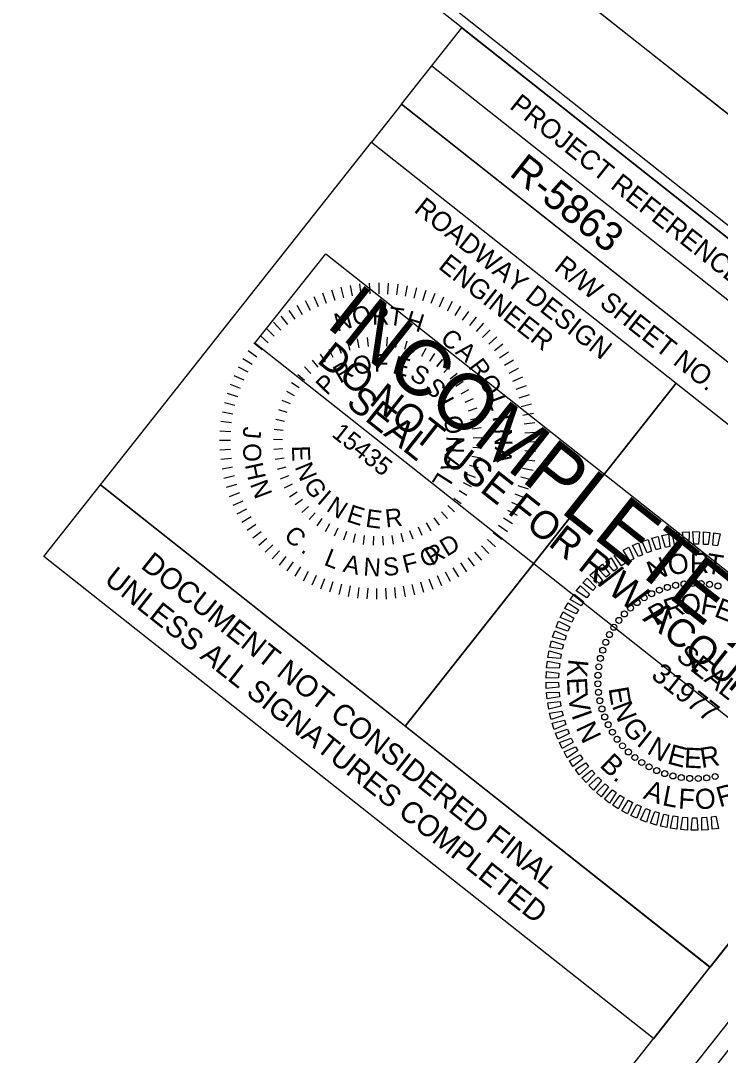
# Model space of a CAD drawing. Extents: x 556999 to 559002, y 505273 to 507273.
# Drawn here: x 558703.1 to 558883.2, y 506079.3 to 506345.6 of the extents above; entities that cross this region are included whole.
import ezdxf

# ---------------------------------------------------------------- set-up
doc = ezdxf.new("R2010")
doc.units = 0
for name, color, linetype in [('Old_Level_21', 7, 'Continuous'), ('Sheet Border Standard 30in CELL', 7, 'Continuous'), ('Sheet Cutting Line CELL', 7, 'Continuous'), ('Sheet Data Field CELL', 7, 'Continuous'), ('Sheet Plot Border Inside CELL', 7, 'Continuous'), ('Sheet Plot Border Outside CELL', 7, 'Continuous'), ('Sheet Sticker Exception Certification CELL', 7, 'Continuous'), ('Sheet Sticker Incomplete CELL', 7, 'Continuous')]:
    doc.layers.add(name, color=color, linetype=linetype)

msp = doc.modelspace()

# ---------------------------------------------------------------- linework, layer by layer
at = {"layer": 'Old_Level_21'}
for p, q in [((558783.1, 506276.32), (558783.91, 506273.67)), ((558785.47, 506276.97), (558786.12, 506274.27)), ((558787.88, 506277.47), (558788.36, 506274.74)), ((558790.31, 506277.83), (558790.63, 506275.07)), ((558792.76, 506278.04), (558792.91, 506275.27)), ((558795.22, 506278.1), (558795.21, 506275.32)), ((558797.68, 506278.01), (558797.5, 506275.24)), ((558800.13, 506277.77), (558799.78, 506275.02)), ((558802.56, 506277.39), (558802.04, 506274.66)), ((558804.96, 506276.85), (558804.28, 506274.17)), ((558807.33, 506276.18), (558806.49, 506273.53)), ((558776.27, 506273.54), (558777.55, 506271.08)), ((558778.49, 506274.61), (558779.61, 506272.07)), ((558780.77, 506275.54), (558781.73, 506272.93)), ((558809.65, 506275.37), (558808.64, 506272.78)), ((558811.92, 506274.41), (558810.76, 506271.89)), ((558814.12, 506273.32), (558812.81, 506270.87)), ((558772.05, 506271.03), (558773.62, 506268.73)), ((558774.12, 506272.35), (558775.54, 506269.96)), ((558816.25, 506272.1), (558814.8, 506269.74)), ((558818.31, 506270.75), (558816.72, 506268.48)), ((558768.16, 506268.02), (558769.99, 506265.93)), ((558770.06, 506269.58), (558771.76, 506267.39)), ((558820.28, 506269.28), (558818.56, 506267.11)), ((558822.16, 506267.7), (558820.31, 506265.63)), ((558766.36, 506266.34), (558768.31, 506264.37)), ((558823.94, 506266), (558821.97, 506264.05)), ((558763.08, 506262.68), (558765.25, 506260.95)), ((558764.67, 506264.56), (558766.73, 506262.71)), ((558787.15, 506263.05), (558787.82, 506260.83)), ((558789.66, 506263.68), (558790.12, 506261.42)), ((558792.23, 506264.07), (558792.47, 506261.77)), ((558794.82, 506264.22), (558794.83, 506261.9)), ((558797.41, 506264.11), (558797.2, 506261.8)), ((558799.98, 506263.75), (558799.54, 506261.48)), ((558802.5, 506263.14), (558801.85, 506260.92)), ((558804.95, 506262.3), (558804.09, 506260.15)), ((558825.62, 506264.2), (558823.53, 506262.37)), ((558827.18, 506262.3), (558824.99, 506260.6)), ((558761.61, 506260.7), (558763.88, 506259.11)), ((558780.14, 506259.73), (558781.42, 506257.81)), ((558782.36, 506261.06), (558783.45, 506259.02)), ((558784.71, 506262.17), (558785.59, 506260.03)), ((558807.31, 506261.22), (558806.24, 506259.16)), ((558809.55, 506259.92), (558808.29, 506257.98)), ((558828.63, 506260.31), (558826.34, 506258.75)), ((558760.26, 506258.65), (558762.63, 506257.2)), ((558778.05, 506258.2), (558779.51, 506256.4)), ((558811.66, 506258.41), (558810.22, 506256.6)), ((558810.22, 506256.6), (558811.66, 506258.41)), ((558829.95, 506258.24), (558827.57, 506256.82)), ((558757.95, 506254.31), (558760.47, 506253.15)), ((558759.04, 506256.51), (558761.49, 506255.21)), ((558774.36, 506254.56), (558776.14, 506253.08)), ((558776.12, 506256.47), (558777.74, 506254.82)), ((558813.61, 506256.7), (558812.01, 506255.03)), ((558815.39, 506254.81), (558813.63, 506253.31)), ((558831.15, 506256.09), (558828.68, 506254.81)), ((558756.99, 506252.04), (558759.59, 506251.04)), ((558772.8, 506252.49), (558774.71, 506251.18)), ((558816.97, 506252.76), (558815.08, 506251.43)), ((558832.21, 506253.87), (558829.67, 506252.75)), ((558756.18, 506249.72), (558758.83, 506248.88)), ((558771.45, 506250.27), (558773.48, 506249.16)), ((558818.36, 506250.57), (558816.34, 506249.43)), ((558833.14, 506251.59), (558830.54, 506250.63)), ((558833.93, 506249.26), (558831.28, 506248.45)), ((558755.51, 506247.35), (558758.2, 506246.67)), ((558770.31, 506247.94), (558772.44, 506247.03)), ((558819.52, 506248.25), (558817.41, 506247.31)), ((558834.57, 506246.89), (558831.88, 506246.24)), ((558754.97, 506244.95), (558757.7, 506244.44)), ((558769.41, 506245.51), (558771.61, 506244.81)), ((558820.46, 506245.83), (558818.26, 506245.1)), ((558835.08, 506244.48), (558832.35, 506244)), ((558754.59, 506242.52), (558757.34, 506242.17)), ((558768.75, 506243.01), (558771.01, 506242.52)), ((558821.15, 506243.33), (558818.89, 506242.82)), ((558835.43, 506242.05), (558832.68, 506241.73)), ((558754.35, 506240.07), (558757.12, 506239.89)), ((558768.32, 506240.45), (558770.62, 506240.18)), ((558821.6, 506240.78), (558819.31, 506240.49)), ((558835.64, 506239.6), (558832.87, 506239.45)), ((558754.27, 506237.62), (558757.04, 506237.6)), ((558768.15, 506237.86), (558770.46, 506237.82)), ((558821.76, 506235.6), (558819.45, 506235.75)), ((558821.81, 506238.19), (558819.5, 506238.12)), ((558835.7, 506237.14), (558832.93, 506237.16)), ((558754.33, 506235.16), (558757.1, 506235.31)), ((558754.54, 506232.71), (558757.29, 506233.03)), ((558768.23, 506235.27), (558770.53, 506235.45)), ((558768.56, 506232.7), (558770.84, 506233.1)), ((558821.47, 506233.03), (558819.18, 506233.4)), ((558835.61, 506234.68), (558832.85, 506234.86)), ((558754.89, 506230.28), (558757.62, 506230.76)), ((558769.13, 506230.17), (558771.36, 506230.79)), ((558820.92, 506230.49), (558818.69, 506231.08)), ((558835.38, 506232.23), (558832.62, 506232.58)), ((558755.39, 506227.86), (558758.09, 506228.51)), ((558769.95, 506227.71), (558772.11, 506228.54)), ((558820.13, 506228.02), (558817.97, 506228.83)), ((558834.46, 506227.4), (558831.77, 506228.08)), ((558834.99, 506229.8), (558832.26, 506230.32)), ((558756.04, 506225.49), (558758.69, 506226.3)), ((558771, 506225.34), (558773.07, 506226.37)), ((558819.12, 506225.63), (558817.03, 506226.65)), ((558833.79, 506225.03), (558831.14, 506225.88)), ((558756.82, 506223.16), (558759.43, 506224.13)), ((558772.28, 506223.07), (558774.24, 506224.31)), ((558775.58, 506222.38), (558773.75, 506220.96)), ((558816.41, 506221.22), (558814.56, 506222.61)), ((558817.87, 506223.36), (558815.9, 506224.57)), ((558832.97, 506222.72), (558830.38, 506223.72)), ((558757.75, 506220.88), (558760.29, 506222.01)), ((558758.82, 506218.67), (558761.28, 506219.94)), ((558775.45, 506218.98), (558777.13, 506220.57)), ((558814.75, 506219.22), (558813.05, 506220.79)), ((558832.02, 506220.45), (558829.49, 506221.6)), ((558760.01, 506216.52), (558762.4, 506217.94)), ((558777.31, 506217.18), (558778.83, 506218.92)), ((558779.34, 506215.57), (558780.69, 506217.45)), ((558810.89, 506215.76), (558809.52, 506217.62)), ((558811.42, 506219.18), (558812.97, 506217.46)), ((558829.7, 506216.11), (558827.34, 506217.56)), ((558830.93, 506218.24), (558828.48, 506219.55)), ((558761.33, 506214.44), (558763.63, 506216.01)), ((558781.52, 506214.16), (558782.68, 506216.16)), ((558783.83, 506212.97), (558784.79, 506215.08)), ((558806.44, 506213.11), (558805.46, 506215.2)), ((558808.73, 506214.33), (558807.55, 506216.31)), ((558828.36, 506214.05), (558826.08, 506215.64)), ((558762.78, 506212.45), (558764.98, 506214.15)), ((558764.35, 506210.56), (558766.43, 506212.38)), ((558786.23, 506212.01), (558786.99, 506214.2)), ((558788.72, 506211.28), (558789.26, 506213.53)), ((558791.27, 506210.8), (558791.59, 506213.09)), ((558793.85, 506210.57), (558793.95, 506212.88)), ((558796.45, 506210.58), (558796.32, 506212.89)), ((558799.03, 506210.85), (558798.68, 506213.13)), ((558801.57, 506211.36), (558801, 506213.6)), ((558804.05, 506212.12), (558803.27, 506214.29)), ((558825.3, 506210.2), (558823.23, 506212.05)), ((558826.89, 506212.08), (558824.71, 506213.8)), ((558766.02, 506208.76), (558767.99, 506210.71)), ((558767.8, 506207.06), (558769.65, 506209.13)), ((558823.6, 506208.42), (558821.65, 506210.39)), ((558769.68, 506205.47), (558771.41, 506207.65)), ((558819.91, 506205.18), (558818.21, 506207.37)), ((558821.81, 506206.74), (558819.98, 506208.83)), ((558771.66, 506204), (558773.25, 506206.28)), ((558773.72, 506202.66), (558775.16, 506205.02)), ((558775.85, 506201.43), (558777.15, 506203.88)), ((558815.85, 506202.41), (558814.42, 506204.79)), ((558817.92, 506203.73), (558816.35, 506206.03)), ((558778.05, 506200.35), (558779.21, 506202.87)), ((558780.32, 506199.39), (558781.32, 506201.98)), ((558782.64, 506198.57), (558783.48, 506201.22)), ((558806.87, 506198.43), (558806.06, 506201.09)), ((558809.2, 506199.22), (558808.23, 506201.82)), ((558811.48, 506200.15), (558810.35, 506202.69)), ((558813.69, 506201.22), (558812.42, 506203.68)), ((558785.01, 506197.9), (558785.69, 506200.59)), ((558787.41, 506197.37), (558787.93, 506200.1)), ((558789.84, 506196.98), (558790.19, 506199.74)), ((558792.29, 506196.75), (558792.47, 506199.52)), ((558794.74, 506196.66), (558794.76, 506199.43)), ((558797.21, 506196.72), (558797.05, 506199.49)), ((558799.65, 506196.93), (558799.34, 506199.69)), ((558802.09, 506197.28), (558801.6, 506200.02)), ((558804.5, 506197.79), (558803.85, 506200.48))]:
    msp.add_line(p, q, dxfattribs=at)
for points in [[(558864.34, 506208.61), (558863.02, 506211.57), (558864.61, 506212.1), (558865.45, 506209.02)], [(558866.67, 506209.4), (558865.56, 506212.44), (558867.18, 506212.86), (558867.8, 506209.73)], [(558869.05, 506210.02), (558868.15, 506213.13), (558869.8, 506213.44), (558870.2, 506210.27)], [(558871.46, 506210.47), (558870.79, 506213.64), (558872.45, 506213.83), (558872.63, 506210.64)], [(558873.9, 506210.76), (558873.45, 506213.96), (558875.12, 506214.04), (558875.08, 506210.84)], [(558876.36, 506210.87), (558876.13, 506214.1), (558877.81, 506214.06), (558877.54, 506210.87)], [(558878.82, 506210.81), (558878.81, 506214.05), (558880.48, 506213.89), (558880, 506210.73)], [(558881.26, 506210.58), (558881.49, 506213.81), (558883.14, 506213.54), (558882.44, 506210.42)], [(558859.87, 506206.57), (558858.16, 506209.31), (558859.65, 506210.06), (558860.92, 506207.12)], [(558862.07, 506207.67), (558860.55, 506210.52), (558862.1, 506211.17), (558863.15, 506208.15)], [(558855.73, 506203.92), (558853.65, 506206.39), (558855.03, 506207.34), (558856.69, 506204.61)], [(558857.76, 506205.31), (558855.85, 506207.93), (558857.3, 506208.78), (558858.76, 506205.94)], [(558852.01, 506200.72), (558849.6, 506202.88), (558850.83, 506204.01), (558852.86, 506201.54)], [(558853.81, 506202.38), (558851.57, 506204.71), (558852.87, 506205.75), (558854.72, 506203.14)], [(558850.32, 506198.93), (558847.77, 506200.92), (558848.92, 506202.14), (558851.11, 506199.81)], [(558848.76, 506197.03), (558846.08, 506198.84), (558847.14, 506200.13), (558849.49, 506197.96)], [(558846.06, 506192.93), (558843.15, 506194.34), (558844.02, 506195.77), (558846.65, 506193.95)], [(558847.34, 506195.02), (558844.53, 506196.64), (558845.5, 506198.01), (558848, 506196.01)], [(558844.93, 506190.74), (558841.93, 506191.95), (558842.7, 506193.44), (558845.44, 506191.81)], [(558843.95, 506188.49), (558840.88, 506189.48), (558841.54, 506191.02), (558844.39, 506189.58)], [(558843.14, 506186.17), (558840, 506186.95), (558840.55, 506188.53), (558843.5, 506187.29)], [(558842.48, 506183.8), (558839.3, 506184.36), (558839.74, 506185.97), (558842.77, 506184.95)], [(558842, 506181.39), (558838.78, 506181.72), (558839.11, 506183.37), (558842.2, 506182.55)], [(558841.68, 506178.95), (558838.45, 506179.06), (558838.67, 506180.72), (558841.81, 506180.13)], [(558841.54, 506176.49), (558838.31, 506176.38), (558838.41, 506178.05), (558841.58, 506177.68)], [(558841.57, 506174.04), (558838.35, 506173.7), (558838.33, 506175.37), (558841.53, 506175.22)], [(558841.77, 506171.59), (558838.58, 506171.02), (558838.45, 506172.69), (558841.64, 506172.76)], [(558842.14, 506169.16), (558839, 506168.37), (558838.75, 506170.03), (558841.93, 506170.32)], [(558842.67, 506166.76), (558839.6, 506165.76), (558839.23, 506167.39), (558842.39, 506167.91)], [(558843.38, 506164.4), (558840.38, 506163.19), (558839.9, 506164.79), (558843.01, 506165.53)], [(558844.24, 506162.1), (558841.34, 506160.68), (558840.75, 506162.25), (558843.8, 506163.2)], [(558845.27, 506159.87), (558842.47, 506158.25), (558841.77, 506159.77), (558844.75, 506160.93)], [(558846.45, 506157.71), (558843.77, 506155.9), (558842.96, 506157.37), (558845.85, 506158.73)], [(558847.77, 506155.64), (558845.22, 506153.65), (558844.32, 506155.06), (558847.11, 506156.62)], [(558849.24, 506153.67), (558846.84, 506151.5), (558845.84, 506152.85), (558848.51, 506154.6)], [(558850.84, 506151.8), (558848.59, 506149.47), (558847.5, 506150.75), (558850.05, 506152.68)], [(558852.57, 506150.05), (558850.49, 506147.57), (558849.31, 506148.77), (558851.71, 506150.87)], [(558854.41, 506148.43), (558852.51, 506145.81), (558851.25, 506146.92), (558853.5, 506149.19)], [(558856.36, 506146.94), (558854.65, 506144.19), (558853.32, 506145.21), (558855.41, 506147.63)], [(558858.42, 506145.58), (558856.9, 506142.73), (558855.5, 506143.65), (558857.41, 506146.21)], [(558860.56, 506144.38), (558859.25, 506141.42), (558857.79, 506142.24), (558859.51, 506144.93)], [(558862.78, 506143.33), (558861.68, 506140.29), (558860.16, 506141), (558861.7, 506143.81)], [(558865.07, 506142.43), (558864.18, 506139.32), (558862.62, 506139.93), (558863.96, 506142.83)], [(558867.42, 506141.7), (558866.75, 506138.53), (558865.15, 506139.03), (558866.28, 506142.02)], [(558869.81, 506141.13), (558869.36, 506137.93), (558867.73, 506138.31), (558868.65, 506141.37)], [(558872.23, 506140.73), (558872.01, 506137.5), (558870.36, 506137.77), (558871.06, 506140.89)], [(558874.68, 506140.5), (558874.68, 506137.26), (558873.02, 506137.42), (558873.5, 506140.58)], [(558877.14, 506140.44), (558877.37, 506137.21), (558875.69, 506137.25), (558875.96, 506140.44)], [(558879.59, 506140.55), (558880.05, 506137.35), (558878.37, 506137.27), (558878.41, 506140.47)], [(558882.04, 506140.84), (558882.71, 506137.67), (558881.05, 506137.48), (558880.86, 506140.67)]]:
    msp.add_lwpolyline(points, close=True, dxfattribs=at)
for centre in [(558871.66, 506200.26), (558873.83, 506200.61), (558876.02, 506200.77), (558878.21, 506200.74), (558880.39, 506200.52), (558865.47, 506198.11), (558867.47, 506199.01), (558869.54, 506199.72), (558882.54, 506200.1), (558861.74, 506195.81), (558863.56, 506197.04), (558858.47, 506192.9), (558860.04, 506194.42), (558857.04, 506191.24), (558854.63, 506187.58), (558855.75, 506189.46), (558853.68, 506185.6), (558852.9, 506183.56), (558851.89, 506179.29), (558852.3, 506181.45), (558851.67, 506177.11), (558851.63, 506174.92), (558851.79, 506172.74), (558852.14, 506170.57), (558852.68, 506168.45), (558853.4, 506166.38), (558854.3, 506164.38), (558855.37, 506162.46), (558856.6, 506160.65), (558857.98, 506158.95), (558859.51, 506157.38), (558861.17, 506155.94), (558862.94, 506154.66), (558864.83, 506153.54), (558866.8, 506152.58), (558868.85, 506151.8), (558870.96, 506151.21), (558873.11, 506150.79), (558875.29, 506150.57), (558877.48, 506150.54), (558879.67, 506150.7), (558881.83, 506151.05)]:
    msp.add_circle(centre, 0.777, dxfattribs=at)
at = {"layer": 'Sheet Border Standard 30in CELL'}
for p, q in [((558808.87, 506333.95), (558965.79, 506209.87)), ((558801.12, 506324.14), (558793.36, 506314.33)), ((558801.12, 506324.14), (558958.04, 506200.06)), ((558801.12, 506324.14), (558958.04, 506200.06)), ((558871.84, 506252.28), (558802.1, 506164.07))]:
    msp.add_line(p, q, dxfattribs=at)
for points in [[(558973.57, 506219.71), (557796.95, 507150.06), (557145.7, 506326.43), (558322.33, 505396.07)], [(558816.65, 506343.79), (558973.57, 506219.71), (558958.04, 506200.06), (558801.12, 506324.14)], [(558793.36, 506314.33), (558871.84, 506252.28), (558802.07, 506164.03), (558723.59, 506226.09)], [(558871.84, 506252.28), (558950.28, 506190.26), (558880.51, 506102.01), (558802.07, 506164.03)]]:
    msp.add_lwpolyline(points, close=True, dxfattribs=at)
at = {"layer": 'Sheet Cutting Line CELL'}
msp.add_line((559002.42, 506228.78), (557681.46, 507273.25), dxfattribs=at)
at = {"layer": 'Sheet Plot Border Inside CELL'}
msp.add_lwpolyline([(558984.96, 506213.96), (557677.73, 507247.58), (557023.32, 506419.94), (558330.55, 505386.32)], close=True, dxfattribs=at)
at = {"layer": 'Sheet Plot Border Outside CELL'}
msp.add_lwpolyline([(559002.42, 506228.78), (557681.46, 507273.25), (556999.2, 506410.4), (558320.16, 505365.92)], close=True, dxfattribs=at)
at = {"layer": 'Sheet Sticker Exception Certification CELL'}
for p, q in [((558709.01, 506207.65), (558723.59, 506226.09)), ((558723.59, 506226.09), (558880.5, 506102.02)), ((558865.92, 506083.58), (558709.01, 506207.65)), ((558880.49, 506102.01), (558865.92, 506083.57))]:
    msp.add_line(p, q, dxfattribs=at)
at = {"layer": 'Sheet Sticker Incomplete CELL'}
msp.add_lwpolyline([(558763.37, 506262.57), (558781.59, 506285.61), (558925.73, 506171.64), (558907.51, 506148.6)], close=True, dxfattribs=at)

# ---------------------------------------------------------------- texts
at = {"layer": 'Old_Level_21'}
for s, height, rotation, p in [('N', 4.62, 15.2636, (558784.48, 506265.54)), ('O', 4.62, 13.3041, (558788.98, 506266.95)), ('R', 4.62, 0.2474, (558793.54, 506267.31)), ('T', 4.62, 352.0864, (558797.58, 506267.4)), ('H', 4.62, 342.6545, (558801.75, 506266.67)), ('C', 4.62, 318.9438, (558810.8, 506263.28)), ('A', 4.62, 318.9438, (558814.7, 506260.07)), ('F', 4.62, 359.8274, (558794, 506255.22)), ('R', 4.62, 30.4199, (558785.27, 506252.09)), ('O', 4.62, 15.1237, (558789.28, 506254.21)), ('E', 4.62, 344.5312, (558798.53, 506254.97)), ('R', 4.62, 306.9345, (558818.12, 506256.49)), ('P', 4.62, 45.7162, (558781.87, 506248.94)), ('S', 4.62, 329.235, (558802.92, 506253.52)), ('O', 4.62, 303.8777, (558820.8, 506252.67)), ('S', 4.62, 313.9387, (558806.77, 506250.95)), ('SEAL', 6.938, 321.5868, (558786.54, 506246.73)), ('L', 4.62, 290.7414, (558823.2, 506248.13)), ('I', 4.62, 298.6425, (558810, 506247.12)), ('O', 4.62, 283.3462, (558811.8, 506243.39)), ('I', 4.62, 281.1659, (558824.46, 506243.71)), ('J', 4.62, 265.5218, (558760.43, 506241.22)), ('15435', 4.622, 321.5868, (558782.88, 506238.78)), ('N', 4.62, 271.8715, (558824.92, 506240.57)), ('O', 4.62, 273.5937, (558760.21, 506236.69)), ('E', 4.62, 271.6569, (558772.88, 506236.17)), ('N', 4.62, 268.05, (558812.67, 506238.75)), ('A', 4.62, 262.1039, (558825.19, 506236)), ('A', 4.62, 252.7537, (558812.3, 506234.21)), ('H', 4.62, 282.2364, (558760.75, 506231.3)), ('N', 4.62, 292.512, (558773.53, 506230.74)), ('G', 4.62, 301.2782, (558775.73, 506226.23)), ('L', 4.62, 237.4575, (558810.63, 506229.7)), ('N', 4.62, 290.909, (558762.02, 506226.31)), ('I', 4.62, 319.373, (558779.12, 506221.65)), ('N', 4.62, 327.0027, (558781.48, 506219.58)), ('E', 4.62, 342.3948, (558786.71, 506216.75)), ('E', 4.62, 352.3806, (558791.65, 506215.35)), ('R', 4.62, 6.1517, (558797.11, 506215.14)), ('C', 4.62, 317.6768, (558770.54, 506212.65)), (' RD', 4.622, 31.2593, (558807.49, 506204.33)), ('.', 4.62, 325.4191, (558774.96, 506208.98)), ('L', 4.62, 338.2034, (558780.87, 506205.61)), ('O ', 4.622, 22.5865, (558806.95, 506204.73)), ('A', 4.62, 347.206, (558785.83, 506203.83)), ('N', 4.62, 356.0286, (558791.16, 506202.82)), ('S', 4.62, 4.9113, (558796.54, 506202.65)), ('F', 4.62, 13.7939, (558802, 506203.33)), ('N', 5.18, 20.2083, (558865.43, 506201.16)), ('O', 5.18, 9.9979, (558870.13, 506202.76)), ('R', 5.18, 359.2727, (558875.29, 506203.52)), ('T', 5.18, 351.0641, (558879.28, 506203.44)), ('P', 5.18, 30.0082, (558866.56, 506189.67)), ('R', 5.18, 18.2459, (558869.63, 506191.45)), ('O', 5.18, 6.1465, (558873.1, 506192.59)), ('F', 5.18, 350.3377, (558877.85, 506192.94)), ('E', 5.18, 338.6598, (558881.33, 506192.36)), ('SEAL', 5.181, 321.6738, (558871.48, 506181.47)), ('K', 5.18, 264.2876, (558844.14, 506181.44)), ('31977', 5.181, 321.6738, (558865.09, 506176.62)), ('E', 5.18, 272.9919, (558843.64, 506176.44)), ('V', 5.18, 280.9718, (558843.85, 506171.83)), ('E', 5.18, 279.5244, (558854.35, 506173.74)), ('N', 5.18, 291.2867, (558855.21, 506169.21)), ('I', 5.18, 289.657, (558844.8, 506166.91)), ('N', 5.18, 295.597, (558845.88, 506163.65)), ('G', 5.18, 306.3367, (558857.63, 506163.84)), ('I', 5.18, 321.3868, (558861.35, 506159.28)), ('N', 5.18, 330.1422, (558864.02, 506157.13)), ('E', 5.18, 345.1923, (558869.27, 506154.46)), ('E', 5.18, 356.9545, (558873.75, 506153.38)), ('R', 5.18, 8.7168, (558878.35, 506153.23)), ('B', 5.18, 315.6938, (558851.89, 506153.77)), ('.', 5.18, 324.0359, (558855.32, 506150.4)), ('A', 5.18, 340.0052, (558863.1, 506145.48)), ('L', 5.18, 349.0526, (558868.01, 506143.71)), ('F', 5.18, 356.5178, (558872.24, 506142.84)), ('O', 5.18, 4.4405, (558876.8, 506142.53)), ('R', 5.18, 15.1656, (558882.97, 506143.12))]:
    msp.add_text(s, height=height, rotation=rotation, dxfattribs=at).set_placement(p)
at = {"layer": 'Sheet Border Standard 30in CELL'}
for s, height, p in [('PROJECT REFERENCE NO.', 5.0001, (558828.67, 506323.2)), ('ROADWAY DESIGN', 5.0001, (558804.05, 506296.58)), ('ENGINEER', 5, (558810.31, 506282)), ('R/W SHEET NO.', 5.0001, (558840.12, 506281.57))]:
    msp.add_text(s, height=height, rotation=321.6667, dxfattribs=at).set_placement(p)
at = {"layer": 'Sheet Data Field CELL'}
msp.add_text('R-5863   ', height=7.5, rotation=321.6667, dxfattribs=at).set_placement((558828.57, 506305.94))
at = {"layer": 'Sheet Sticker Exception Certification CELL'}
for s, p in [('DOCUMENT NOT CONSIDERED FINAL', (558733.7, 506204.9)), ('UNLESS ALL SIGNATURES COMPLETED', (558724.26, 506201.15))]:
    msp.add_text(s, height=5.5, rotation=321.6667, dxfattribs=at).set_placement(p)
at = {"layer": 'Sheet Sticker Incomplete CELL'}
for s, height, p in [('INCOMPLETE PLANS', 14.4, (558781.24, 506267.11)), ('DO NOT USE FOR R/W ACQUISITION', 7.2, (558779.04, 506257.77))]:
    msp.add_text(s, height=height, rotation=321.6667, dxfattribs=at).set_placement(p)

doc.saveas('drawing.dxf')
